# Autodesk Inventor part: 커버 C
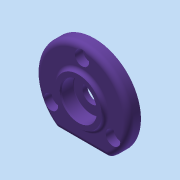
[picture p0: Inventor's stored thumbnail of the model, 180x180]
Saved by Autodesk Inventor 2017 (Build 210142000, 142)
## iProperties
Created: 2020-04
Part Number: 커버 C
Material: 알루미늄 6061
Document SubType Name: Modeling
Designer: mduedu
Density: 2.71 g/cm^3
Appearance: 보라색
Mass: 35.2376 g
Surface Area: 62.3739 cm^2
Volume: 13.0028 cm^3
Author: mduedu
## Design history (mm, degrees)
sketch "스케치1"
  geometry: C1 r 26 at (0, 0); 1 further point
  constraints: 1 centre point, 1 coincident
  dimensions: "d0" = 52 diameter of C1
extrude "돌출1" new body sketch "스케치1" distance "d1" = 7; taper "d2" = 0 deg
sketch "스케치2"
  geometry: L1 (-14.62, -21.5)-(14.62, -21.5); A1 r 26 centre (0, 0) between (-14.62, -21.5) and (14.62, -21.5) reference; 1 further point
  constraints: 2 end point, 2 point on circle, 1 horizontal
  dimensions: "d3" = 21.5 distance from line of L1 point (0, 0)
extrude "돌출2" cut sketch "스케치2" stored distance "d4" = 7; taper "d5" = 0 deg
sketch "스케치6"
  geometry: C1 r 13 at (0, 0); 1 further point
  constraints: 1 centre point, 1 coincident
  dimensions: "d29" = 26 diameter of C1
extrude "돌출5" join sketch "스케치6" distance "d30" = 2; taper "d31" = 0 deg
fillet "모깎기1" dims "d6" = 3
fillet "모깎기2" dims "d7" = 3
fillet "모깎기4" dims "d33" = 2
sketch "스케치3" dims "d8" = 40
  geometry: 3 further points
  constraints: 2 vertical alignment, 1 coincident, 2 other
hole "구멍1" sketch "스케치3" at (0, 20) diameter "d9" = 4.5; stored, may be unused: countersink angle "d13" = 90 deg, drill point angle "d15" = 118 deg; dims "d10" = 6, "d11" = 8, "d12" = 4.4, "d14" = 8
sketch "스케치4"
  geometry: C1 r 14 at (0, 0); 1 further point
  constraints: 1 centre point, 1 coincident
  dimensions: "d19" = 28 diameter of C1
extrude "돌출3" join sketch "스케치4" distance "d20" = 4; taper "d21" = 0 deg
sketch "스케치5"
  geometry: C1 r 12 at (0, 0); 1 further point
  constraints: 1 centre point, 1 coincident
  dimensions: "d22" = 24 diameter of C1
extrude "돌출4" cut sketch "스케치5" distance "d23" = 3; taper "d24" = 0 deg
fillet "모깎기3" dims "d25" = 3
chamfer "모따기1" distance "d26" = 0.5; stored, may be unused: second distance "d27" = 2, angle "d28" = 45 deg
sketch "스케치7"
  geometry: 2 further points
  constraints: 1 coincident
hole "구멍2" sketch "스케치7" at (0, 0) diameter "d34" = 10; stored, may be unused: countersink angle "d38" = 90 deg, drill point angle "d40" = 118 deg; dims "d35" = 6, "d36" = 20, "d37" = 7.3, "d39" = 8
fillet "모깎기5" dims "d41" = 0.3
chamfer "모따기2" distance "d42" = 0.7; stored, may be unused: second distance "d43" = 2, angle "d44" = 30 deg
node "솔리드1"
pattern_circular "원형 패턴1" dims angle "d17" = 360 deg
node "투영된 루프1"
